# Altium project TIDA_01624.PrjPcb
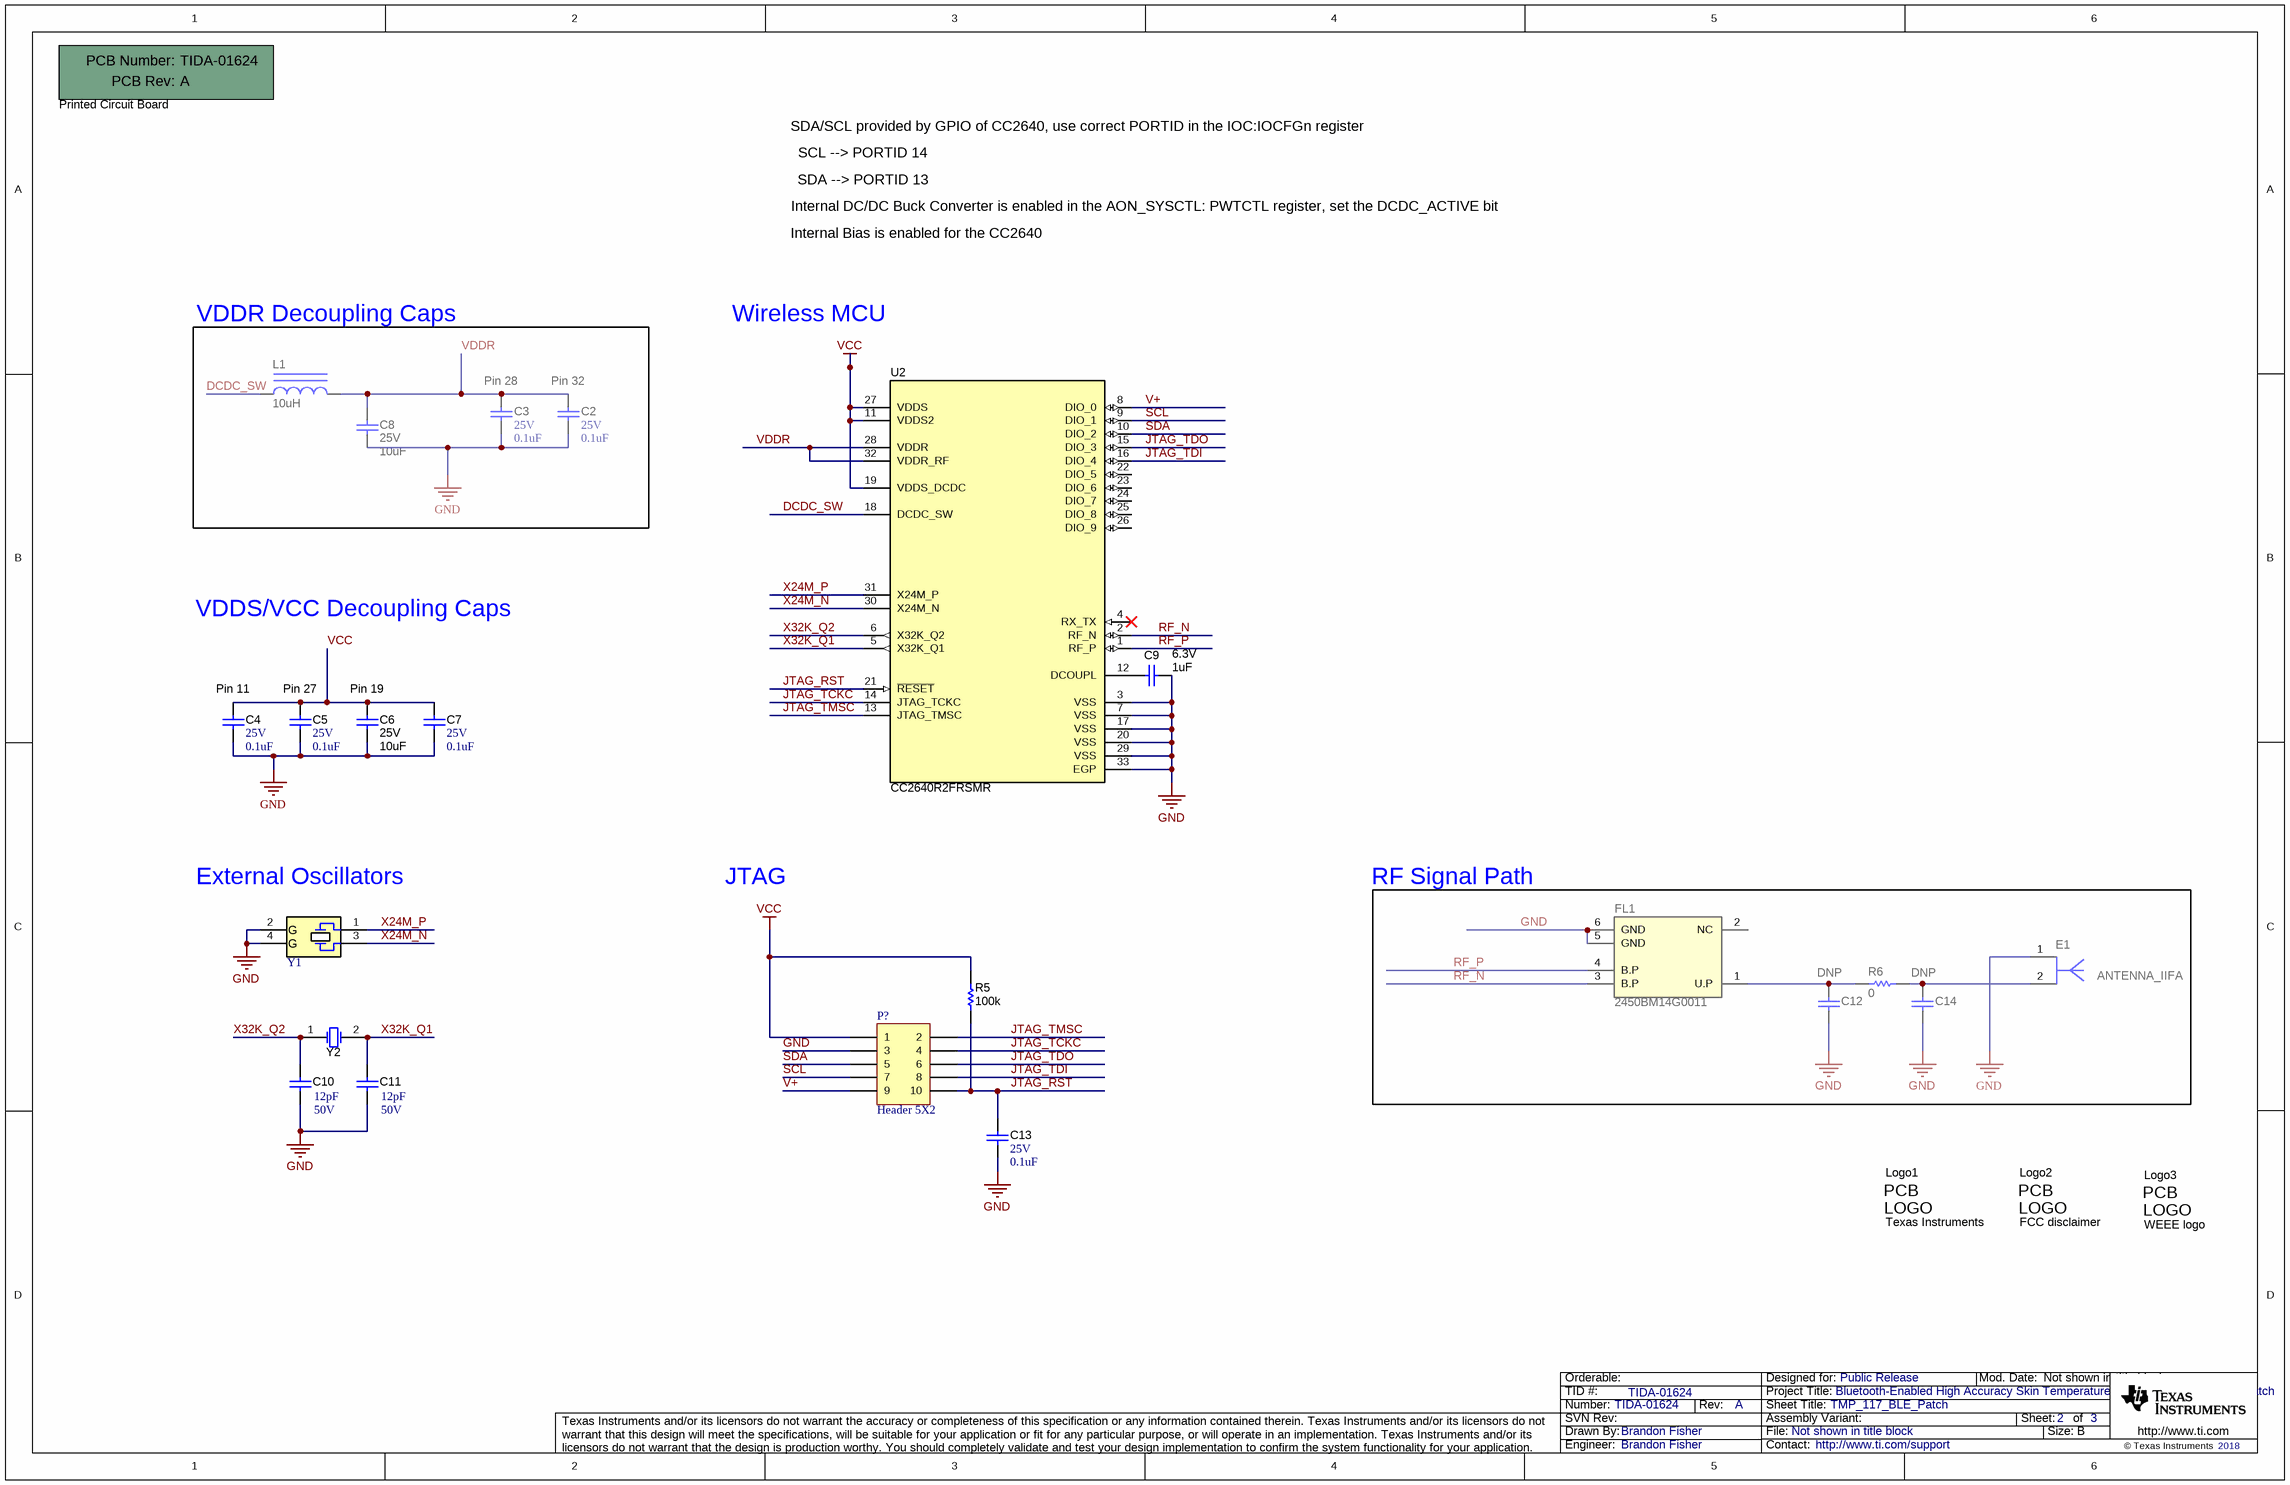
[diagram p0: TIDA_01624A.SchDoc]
CopyrightYear: 2018; PCB_Layout: Brandon Fisher; PCB_Rev: A; PRJ_Customer: Public Release; PRJ_Engineer: Brandon Fisher; PRJ_Number: TIDA-01624; PRJ_Title: Bluetooth-Enabled High Accuracy Skin Temperature Measurement Flex PCB Patch; SCH_Rev: A; TechSupport: http://www.ti.com/support; TID: TIDA-01624
1 sheet, 26 parts. Net scope: global (net labels, ports and power ports of the same name join across sheets).
Board file: TIDA_0162411.PcbDoc

## Sheet TIDA_01624A.SchDoc: TMP_117_BLE_Patch
size 431 x 279 mm; Date: Not shown in title block; ApprovedBy: Not shown in title block; CheckedBy: Not shown in title block; Author: Not shown in title block; CompanyName: Not shown in title block; DrawnBy: Brandon Fisher; Engineer: Not shown in title block; Organization: Not shown in title block; Address1: Not shown in title block; Address2: Not shown in title block; Address3: Not shown in title block; Address4: Not shown in title block; DocumentNumber: 1; Revision: Use project parameter SCH_Rev; SheetNumber: 2; SheetTotal: 3; PageSetup: Record=PageOptions¦CenterHorizontal=True¦CenterVertical=True¦PrintScale=1.00¦XCorrection=1.00¦YCorrection=1.00¦PrintKind=0¦BorderSize=5000000¦LeftOffset=0¦BottomOffset=0¦Orientation=2¦PaperLength=1000¦PaperWidth=1000¦Scale=100¦PaperSource=15¦PrintQuality=600¦MediaType=1¦DitherType=10¦PaperKind=Letter¦PrintScaleMode=1

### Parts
!PCB1  Printed Circuit Board  (mechanical)
C2  VDC_V: 25V  ValueDisplayed: 0.1uF  [0402]  (hidden comment: GRM155R71E104KE14D)
C3  VDC_V: 25V  ValueDisplayed: 0.1uF  [0402]  (hidden comment: GRM155R71E104KE14D)
C4  VDC_V: 25V  ValueDisplayed: 0.1uF  [0402]  (hidden comment: GRM155R71E104KE14D)
C5  VDC_V: 25V  ValueDisplayed: 0.1uF  [0402]  (hidden comment: GRM155R71E104KE14D)
C6  VDC_V: 25V  ValueDisplayed: 10uF  [0603]  (hidden comment: C1608X5R1E106M080AC)
C7  VDC_V: 25V  ValueDisplayed: 0.1uF  [0402]  (hidden comment: GRM155R71E104KE14D)
C8  VDC_V: 25V  ValueDisplayed: 10uF  [0603]  (hidden comment: C1608X5R1E106M080AC)
C9  VDC_V: 6.3V  ValueDisplayed: 1uF  [0402]  (hidden comment: GRM152R60J105ME15D)
C10  VDC_V: 50V  ValueDisplayed: 12pF  [CAPC0402(1005)33_L]  (hidden comment: GRM155R71E104KE14D)
C11  VDC_V: 50V  ValueDisplayed: 12pF  [CAPC0402(1005)33_L]  (hidden comment: GRM155R71E104KE14D)
C12  DNP  [0201_033]
C13  VDC_V: 25V  ValueDisplayed: 0.1uF  [0402]  (hidden comment: GRM155R71E104KE14D)
C14  DNP  [0201_033]
E1  ANTENNA_IIFA  [ANTENNA_IIFA]  (net tie)
FL1  2450BM14G0011  [Johanson_2450BM14G0011]
L1  ValueDisplayed: 10uH  [0805_HV]  (hidden comment: CKS2125100M-T)
Logo1  Texas Instruments  [TI_Symbol_Overlay_Small]  (no BOM)
Logo2  FCC disclaimer  [FCC_disclaimer]  (no BOM)
Logo3  WEEE logo  [WEEE_Minimum]  (no BOM)
P?  Header 5X2  [HDR2X5]
R5  ValueDisplayed: 100k  [0402]  (hidden comment: ERJ-2RKF1003X)
R6  ValueDisplayed: 0  [0201]  (hidden comment: CRCW02010000Z0ED)
U2  CC2640R2FRSMR  [RSM0032B_NV]
Y1  TSX-3225 24.0000MF15X-AC3  [EPSON_TSX-3225]  (value not drawn)
Y2  CM2012H32768DZFT  [CM2012H]  (value not drawn)

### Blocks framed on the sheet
VDDR Decoupling Caps: C2 C3 C8 L1
RF Signal Path: C12 C14 E1 FL1 R6

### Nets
GND: C2.1 C3.1 C4.1 C5.1 C6.2 C7.2 C8.2 C9.1 C10.2 C11.2 C12.2 C13.2 C14.2 E1.1 FL1.5(GND) FL1.6(GND) P?.3 U2.3(VSS) U2.7(VSS) U2.17(VSS) U2.20(VSS) U2.29(VSS) U2.33(EGP) Y1.2(GND) Y1.4(GND)
VCC: C4.2 C5.2 C6.1 C7.1 P?.1 R5.2 U2.11(VDDS2) U2.19(VDDS_DCDC) U2.27(VDDS)
DCDC_SW: L1.1 U2.18(DCDC_SW)
JTAG_RST: C13.1 P?.10 R5.1 U2.21(~{RESET})
JTAG_TCKC: P?.4 U2.14(JTAG_TCKC)
JTAG_TDI: P?.8 U2.16(DIO_4)
JTAG_TDO: P?.6 U2.15(DIO_3)
JTAG_TMSC: P?.2 U2.13(JTAG_TMSC)
RF_N: FL1.3(B.P) U2.2(RF_N)
RF_P: FL1.4(B.P) U2.1(RF_P)
SCL: P?.7 U2.9(DIO_1)
SDA: P?.5 U2.10(DIO_2)
V+: P?.9 U2.8(DIO_0)
VDDR: C2.2 C3.2 C8.1 L1.2 U2.28(VDDR) U2.32(VDDR_RF)
X24M_N: U2.30(X24M_N) Y1.3
X24M_P: U2.31(X24M_P) Y1.1
X32K_Q1: C11.1 U2.5(X32K_Q1) Y2.2(OSC2)
X32K_Q2: C10.1 U2.6(X32K_Q2) Y2.1(OSC1)
NetC9_2: C9.2 U2.12(DCOUPL)
NetC12_1: C12.1 FL1.1(U.P) R6.1
NetC14_1: C14.1 E1.2 R6.2

Not connected (* = marked no-connect by the designer): FL1 2(NC); U2 4(RX_TX)* 22(DIO_5) 23(DIO_6) 24(DIO_7) 25(DIO_8) 26(DIO_9)

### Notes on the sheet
- SCL --> PORTID 14
- SDA/SCL provided by GPIO of CC2640, use correct PORTID in the IOC:IOCFGn register
- SDA --> PORTID 13
- Internal Bias is enabled for the CC2640
- Internal DC/DC Buck Converter is enabled in the AON_SYSCTL: PWTCTL register, set the DCDC_ACTIVE bit
- Wireless MCU
- (near C3) Pin 28
- (near C2) Pin 32
- VDDS/VCC Decoupling Caps
- (near C4) Pin 11
- (near C5) Pin 27
- (near C6) Pin 19
- (near Y1) External Oscillators
- JTAG

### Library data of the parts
!PCB1 = CMP-0003618-2: Manufacturer: Any; PartNumber: TIDA-01624
C2-C5 C7 C13 = CMP-0006659-2: CAP, CERM, 0.1 uF, 25 V, +/- 10%, X7R, 0402; Manufacturer: MuRata; TaMin_C: -55°C; Polarized: N; SizeAreaWB_mm2: 3; Value1: Unknown; U/M: EA; Value: 0.1uF; TaMax_C: 125°C; SizeZ_mm: 0.6; SizeX_mm: 1; SizeY_mm: 0.5; CompType: Capacitor; Cap_F: 100nF; AEC Category: Q200
C6 = CMP-0007007-5: CAP, CERM, 10 uF, 25 V, +/- 20%, X5R, 0603; Manufacturer: TDK; TaMin_C: -55°C; Polarized: N; SizeAreaWB_mm2: 4.68; Value1: 0.004639 ohm; U/M: EA; Value: 10uF; TaMax_C: 85°C; SizeZ_mm: 1; SizeX_mm: 1.6; SizeY_mm: 0.8; SizeArea_mm2: 1.28; CompType: Capacitor; Cap_F: 10µF; AEC Category: Q200; ESR_ohm: 4.639m; IRMS_A: 2.41407A
C8 = CMP-0007007-5: CAP, CERM, 10 uF, 25 V, +/- 20%, X5R, 0603; Manufacturer: TDK; TaMin_C: -55°C; Polarized: N; SizeAreaWB_mm2: 4.68; Value1: 0.004639 ohm; U/M: EA; Value: 10uF; TaMax_C: 85°C; SizeZ_mm: 1; SizeX_mm: 1.6; SizeY_mm: 0.8; SizeArea_mm2: 1.28; Cap_F: 10µF; AEC Category: Q200; ESR_ohm: 4.639m; IRMS_A: 2.41407A
C9 = CMP-0006372-2: CAP, CERM, 1 uF, 6.3 V, +/- 20%, X5R, 0402; Manufacturer: MuRata; TaMin_C: -55°C; Polarized: N; SizeAreaWB_mm2: 3; Value1: Unknown; U/M: EA; Value: 1uF; TaMax_C: 85°C; SizeZ_mm: 0.6; SizeX_mm: 1; SizeY_mm: 0.5; CompType: Capacitor; Cap_F: 1µF; AEC Category: Q200
C10 C11 = CMP-0006659-2: CAP, CERM, 12 pF, 50 V, +/- 5%, C0G/NP0, 0201; Manufacturer: MuRata; TaMin_C: -55°C; Polarized: N; TempCo: X7R; SizeAreaWB_mm2: 3; Value1: Unknown; U/M: EA; Value: 0.1uF; TaMax_C: 125°C; Tolerance_%: 10%; SizeZ_mm: 0.6; SizeX_mm: 1; SizeY_mm: 0.5; Cap_Case: 0402; Value2: 25V; CompType: Capacitor; Cap_F: 100nF; AEC Category: Q200
C12 C14 = CMP-0009654-3: CAP, CERM, 470 pF, 50 V, +/- 10%, X7R, AEC-Q200 Grade 1, 0201; SizeAreaWB_mm2: 2.08; U/M: EA; SizeZ_mm: 0.33; SizeX_mm: 0.6; SizeY_mm: 0.3; SizeArea_mm2: 0.18
E1 = CMP-0001736-1: PCB Antenna.  There is nothing to buy or mount.
FL1 = CMP-0001890-2: 2.4GHz Impedance Matched Balun + embedded FCC/ETSI Band Pass Filter, SMD; Manufacturer: Johanson Technology; SizeZ_mm: 0.7; SizeX_mm: 1.6; SizeY_mm: 0.8; SizeAreaWB_mm2: 4.68; SizeArea_mm2: 1.28
L1 = CMP-0059606-1: Inductor, Multilayer, Ferrite, 10 uH, 0.11 A, 0.52 ohm, SMD; Manufacturer: Taiyo Yuden; Green_Lifecycle: Active; SizeAreaWB_mm2: 6.75; DCR_ohm: 5.2d; Green_REACh: Passed; Value: 10uH; Imax_A: 1.1dA; SizeZ_mm: 1.45; SizeX_mm: 2; SizeY_mm: 1.25; Value2: 0.11A; SizeArea_mm2: 2.5; Ind_H: 10µH; AEC Category: Q200
Logo1 = CMP-0074838-1: Texas Instrument Corporate Signature; SymbolCreator: a0412235; Lib Reference: TI_Logo
Logo2 = CMP-0074847-1: FCC_disclaimer
Logo3 = CMP-0074769-1
P? = Header 5X2: Header, 5-Pin, Dual row
R5 = CMP-0026659-1: RES, 100 k, 1%, 0.1 W, 0402; Manufacturer: Panasonic; Power_W: 100mW; TempCo: 100 ppm/C; U/M: EA; Value: 100k; EIA_Code: E96; SizeX_mm: 1; SizeY_mm: 0.5; SizeZ_mm: 0.6; Value2: 0.1W; VDC_V: 50V; AEC Category: Q200
R6 = CMP-0027008-4: RES, 0, 5%, 0.05 W, 0201; Manufacturer: Vishay-Dale; Power_W: 50mW; TempCo: ppm/C; Value_Code: 0000; Value: 0; EIA_Code: E24; SizeX_mm: 0.6; SizeY_mm: 0.3; SizeZ_mm: 0.26; Value2: 0.05W; SizeArea_mm2: 0.18; AEC Qualified: N; AEC Category: Q200
U2 = CMP-0076686-1: SimpleLink(TM) Bluetooth(R) low energy Wireless MCU, RSM0032B (VQFN-32); Manufacturer: Texas Instruments; Alternate PartNumber: CC2640R2FRSMT; SizeAreaWB_mm2: 25.0; SizeArea_mm2: 16.0; SizeZ_mm: 1.0; SizeY_mm: 4.0; U/M: EA; CompType: IC
Y1 = CMP-0079304-1: Crystal, 24 MHz, 10 ppm, 9 pF, SMD; Manufacturer: Epson; TaMin_C: -40°C; Frequency Stability: 15 ppm; Frequency_Fixed: 24MHz; TaMax_C: 85°C; AEC Category: Q200; AEC Qualified: N; Frequency Tolerance: 10 ppm; Load Capacitance: 9 pF
Y2 = CMP-0004654-3: Crystal, 32.768 kHz, SMD; Manufacturer: Citizen Electronics; TaMax_C: 85°C; TaMin_C: -40°C; Frequency Stability: +/-20ppm

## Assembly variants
001: not fitted C12 C14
